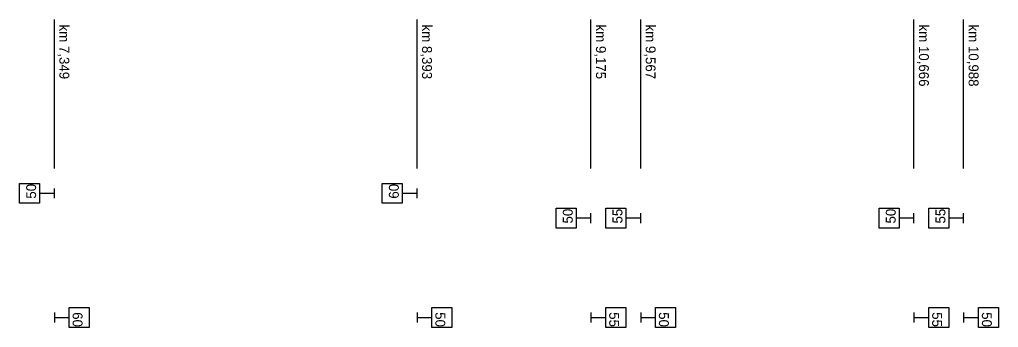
# Model space of a CAD drawing. Extents: x -1424 to 5155, y -2900 to 2050.
# Drawn here: x 2680 to 2877, y 1988 to 2050 of the extents above; entities that cross this region are included whole.
import ezdxf

# ---------------------------------------------------------------- set-up
doc = ezdxf.new("R2010")
doc.units = 0
doc.layers.add('rychlostník', color=7, linetype='Continuous')

msp = doc.modelspace()

# ---------------------------------------------------------------- linework, layer by layer
at = {"layer": 'rychlostník'}
for p, q in [((2687, 2020), (2687, 2050)), ((2760, 2020), (2760, 2050)), ((2795, 2020), (2795, 2050)), ((2795, 2020), (2795, 2050)), ((2805, 2020), (2805, 2050)), ((2805, 2020), (2805, 2050)), ((2860, 2020), (2860, 2050)), ((2860, 2020), (2860, 2050)), ((2870, 2020), (2870, 2050)), ((2870, 2020), (2870, 2050)), ((2680, 2013), (2680, 2017)), ((2680, 2017), (2684, 2017)), ((2684, 2017), (2684, 2013)), ((2687, 2014), (2687, 2016)), ((2753, 2013), (2753, 2017)), ((2753, 2017), (2757, 2017)), ((2757, 2017), (2757, 2013)), ((2760, 2014), (2760, 2016)), ((2687, 2015), (2684, 2015)), ((2760, 2015), (2757, 2015)), ((2684, 2013), (2680, 2013)), ((2757, 2013), (2753, 2013)), ((2788, 2008), (2788, 2012)), ((2788, 2012), (2792, 2012)), ((2792, 2012), (2792, 2008)), ((2798, 2008), (2798, 2012)), ((2798, 2012), (2802, 2012)), ((2802, 2012), (2802, 2008)), ((2853, 2008), (2853, 2012)), ((2853, 2012), (2857, 2012)), ((2857, 2012), (2857, 2008)), ((2863, 2008), (2863, 2012)), ((2863, 2012), (2867, 2012)), ((2867, 2012), (2867, 2008)), ((2790.33, 2010.09), (2790.33, 2010.09)), ((2795, 2010), (2792, 2010)), ((2795, 2009), (2795, 2011)), ((2800.33, 2010.09), (2800.33, 2010.09)), ((2805, 2010), (2802, 2010)), ((2805, 2009), (2805, 2011)), ((2855.33, 2010.09), (2855.33, 2010.09)), ((2860, 2010), (2857, 2010)), ((2860, 2009), (2860, 2011)), ((2865.33, 2010.09), (2865.33, 2010.09)), ((2870, 2010), (2867, 2010)), ((2870, 2009), (2870, 2011)), ((2792, 2008), (2788, 2008)), ((2802, 2008), (2798, 2008)), ((2857, 2008), (2853, 2008)), ((2867, 2008), (2863, 2008)), ((2690, 1992), (2694, 1992)), ((2690, 1988), (2690, 1992)), ((2694, 1992), (2694, 1988)), ((2763, 1992), (2767, 1992)), ((2763, 1988), (2763, 1992)), ((2767, 1992), (2767, 1988)), ((2798, 1992), (2802, 1992)), ((2798, 1988), (2798, 1992)), ((2802, 1992), (2802, 1988)), ((2808, 1992), (2812, 1992)), ((2808, 1988), (2808, 1992)), ((2812, 1992), (2812, 1988)), ((2863, 1992), (2867, 1992)), ((2863, 1988), (2863, 1992)), ((2867, 1992), (2867, 1988)), ((2873, 1992), (2877, 1992)), ((2873, 1988), (2873, 1992)), ((2877, 1992), (2877, 1988)), ((2687, 1991), (2687, 1989)), ((2687, 1990), (2690, 1990)), ((2760, 1991), (2760, 1989)), ((2760, 1990), (2763, 1990)), ((2795, 1991), (2795, 1989)), ((2795, 1990), (2798, 1990)), ((2799.67, 1989.91), (2799.67, 1989.91)), ((2805, 1991), (2805, 1989)), ((2805, 1990), (2808, 1990)), ((2809.67, 1989.91), (2809.67, 1989.91)), ((2860, 1991), (2860, 1989)), ((2860, 1990), (2863, 1990)), ((2864.67, 1989.91), (2864.67, 1989.91)), ((2870, 1991), (2870, 1989)), ((2870, 1990), (2873, 1990)), ((2874.67, 1989.91), (2874.67, 1989.91)), ((2694, 1988), (2690, 1988)), ((2767, 1988), (2763, 1988)), ((2802, 1988), (2798, 1988)), ((2812, 1988), (2808, 1988)), ((2867, 1988), (2863, 1988)), ((2877, 1988), (2873, 1988))]:
    msp.add_line(p, q, dxfattribs=at)

# ---------------------------------------------------------------- texts
for s, rotation, p in [('km 7,349', 270, (2688, 2049)), ('km 8,393', 270, (2761, 2049)), ('km 9,175', 270, (2796, 2049)), ('km 9,567', 270, (2806, 2049)), ('km 10,666', 270, (2861, 2049)), ('km 10,988', 270, (2871, 2049)), ('50', 90, (2683.33, 2013.93)), ('60', 90, (2756.33, 2013.93)), ('50', 90, (2791.33, 2008.93)), ('55', 90, (2801.33, 2008.93)), ('50', 90, (2856.33, 2008.93)), ('55', 90, (2866.33, 2008.93)), ('60', 270, (2690.67, 1991.07)), ('50', 270, (2763.67, 1991.07)), ('55', 270, (2798.67, 1991.07)), ('50', 270, (2808.67, 1991.07)), ('55', 270, (2863.67, 1991.07)), ('50', 270, (2873.67, 1991.07))]:
    msp.add_text(s, height=2, rotation=rotation, dxfattribs=at).set_placement(p)

doc.saveas('drawing.dxf')
